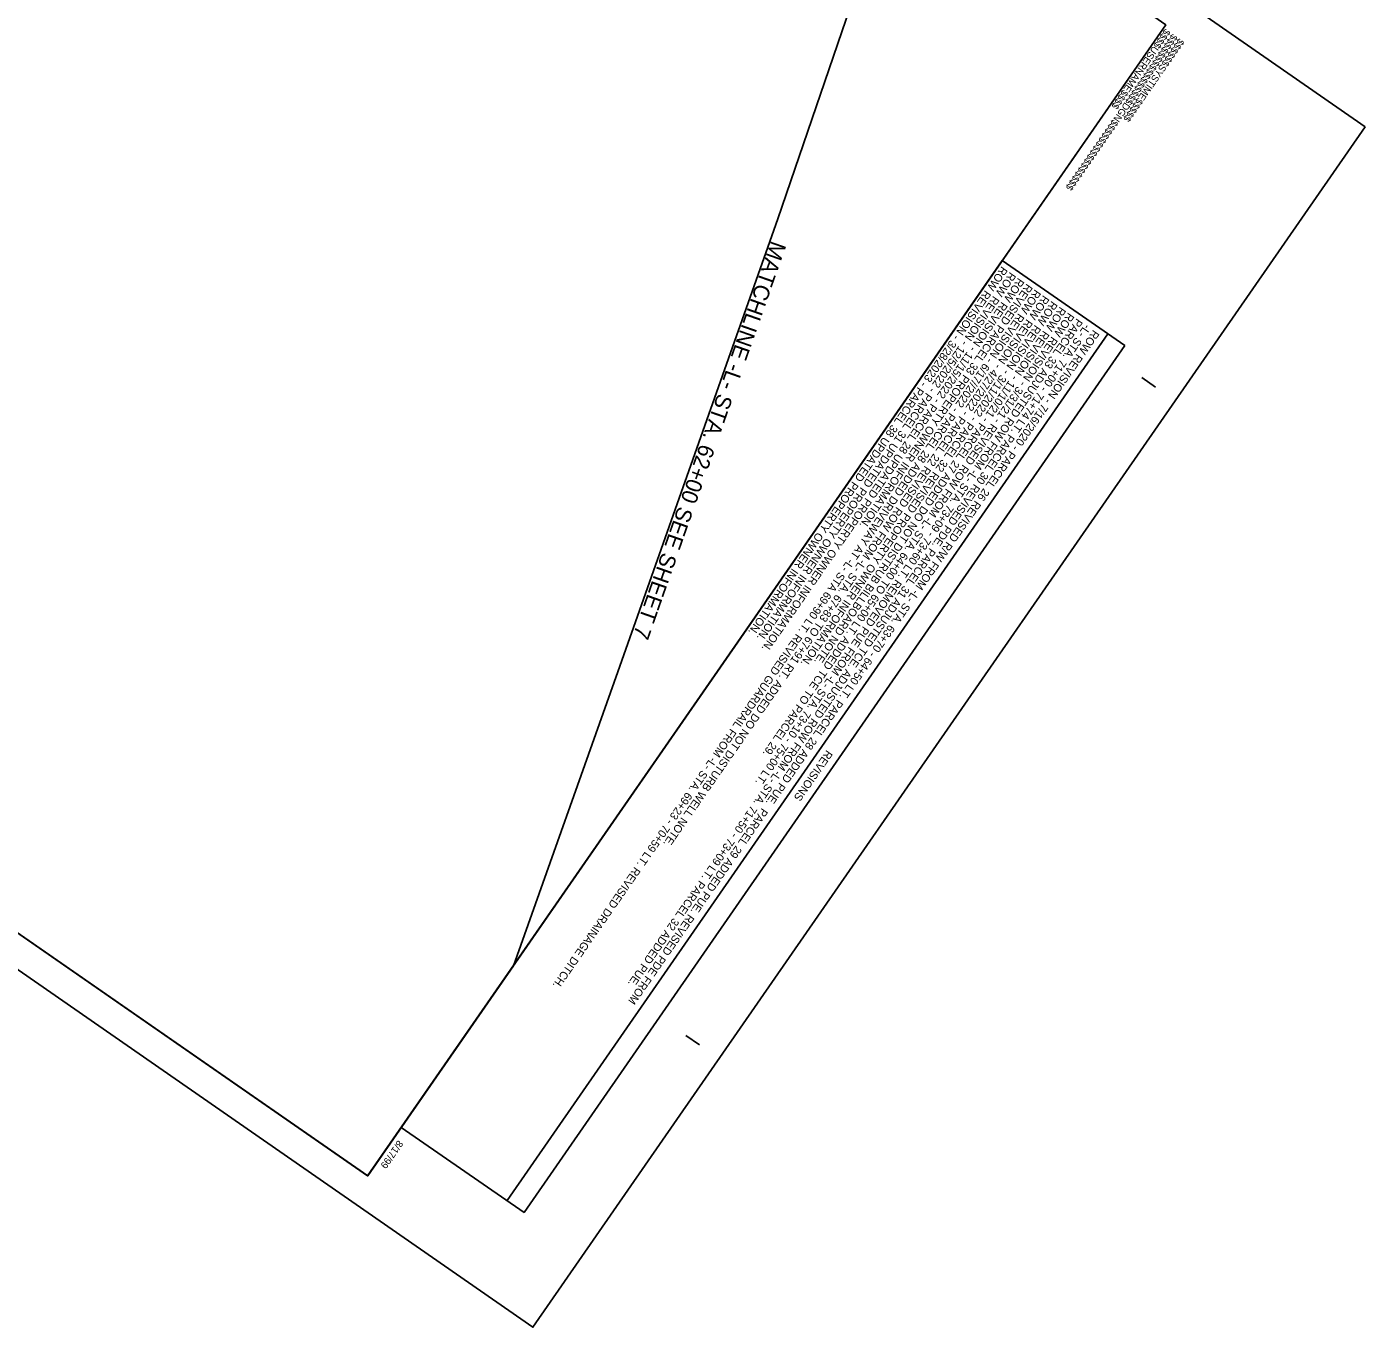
# Model space of a CAD drawing. Extents: x 478372 to 480379, y 492840 to 494699.
# Drawn here: x 479376 to 480379, y 492840 to 493814 of the extents above; entities that cross this region are included whole.
import ezdxf

# ---------------------------------------------------------------- set-up
doc = ezdxf.new("R2010")
doc.units = 0
for name, color, linetype in [('Matchline', 7, 'Continuous'), ('Matchline Text', 7, 'Continuous'), ('Sheet Block Revision CELL', 7, 'Continuous'), ('Sheet Clip Boundary CELL', 7, 'Continuous'), ('Sheet Plan CELL', 7, 'Continuous'), ('Sheet Plot Border Outside CELL', 7, 'Continuous')]:
    doc.layers.add(name, color=color, linetype=linetype)

msp = doc.modelspace()

# ---------------------------------------------------------------- linework, layer by layer
at = {"layer": 'Matchline'}
msp.add_line((479938.9, 493670.6), (479819.1, 493331.1), dxfattribs=at)
at = {"layer": 'Sheet Block Revision CELL'}
msp.add_line((480186.5, 493584.3), (479735.9, 492934.7), dxfattribs=at)
msp.add_lwpolyline([(480199.3, 493575.5), (479748.7, 492925.8), (479656.6, 492989.6), (480107.3, 493639.3)], close=True, dxfattribs=at)
at = {"layer": 'Sheet Clip Boundary CELL'}
msp.add_lwpolyline([(479740.7, 493110.7), (479819.1, 493331.1), (479938.9, 493670.6), (480035, 493951.1), (479137.5, 494573.7), (479091.9, 494507.9), (479078.6, 494420.5), (478969, 494336.5), (478682.9, 494117.9), (478570.3, 494055.3), (478497.8, 493950.7), (478662.1, 493836.7), (478563.2, 493694.1), (479631.4, 492953.2)], close=True, dxfattribs=at)
at = {"layer": 'Sheet Plan CELL'}
for p, q in [((480222.2, 493544.4), (480211.9, 493551.5)), ((479880.2, 493051.4), (479869.9, 493058.5)), ((479631.3, 492953.2), (479631.3, 492953.2))]:
    msp.add_line(p, q, dxfattribs=at)
for points in [[(478398.8, 493808.2), (479631.3, 492953.2), (480229.8, 493815.9), (478997.3, 494670.9)], [(480229.8, 493815.9), (479631.4, 492953.2), (478563.2, 493694.1), (478648.7, 493817.4), (478484.4, 493931.4), (478997.3, 494670.9)]]:
    msp.add_lwpolyline(points, close=True, dxfattribs=at)
at = {"layer": 'Sheet Plot Border Outside CELL'}
msp.add_lwpolyline([(480379.4, 493739.5), (478996.2, 494699.1), (478372.1, 493799.4), (479755.3, 492839.8)], close=True, dxfattribs=at)

# ---------------------------------------------------------------- texts
at = {"layer": 'Matchline Text'}
msp.add_text('MATCHLINE -L- STA. 62+00 SEE SHEET 7', height=12, rotation=250.6658, dxfattribs=at).set_placement((479934.2, 493654.7))
at = {"layer": 'Sheet Block Revision CELL'}
for s, p in [('ROW REVISION - 3/28/2023 - PARCEL 38 UPDATED PROPERTY OWNER INFORMATION.  ', (480106.8, 493635.4)), ('ROW REVISION - 12/5/2022 - PARCEL 31 UPDATED PROPERTY OWNER INFORMATION.', (480113.1, 493631.1)), ('ROW REVISION - 6/17//2022 - PARCEL 28 ADDED DRIVEWAY AT -L- STA 69+90 LT. REVISED GUARDRAIL FROM -L- STA. 69+23 - 70+59 LT. REVISED DRAINAGE DITCH.', (480131.8, 493618.1)), ('ROW REVISION - 11/15/2022 - PARCEL 28 UPDATED PROPERTY OWNER INFORMATION. ', (480119.3, 493626.7)), ('REVISED PARCEL 33 PROPERTY OWNER INFORMATION.', (480125.6, 493622.4)), ('ROW REVISION - 4/27/2022 - PARCEL 22 REVISED ROW FROM -L- STA. 67+83 TO 67+91 RT. ADDED DO NOT DISTURB WELL NOTE.', (480138.1, 493613.7)), ('ROW REVISION - 3/11/2022 - PARCEL 32 REVISED PROPERTY OWNER INFORMATION.  ', (480144.3, 493609.4)), ('ROW REVISION - 3/31/21 - REVISED ROW FROM -L- STA. 64+00 TO 65+00 LT. ADDED TCE TO PARCEL 29.', (480156.8, 493600.7)), ('ROW REVISION - 11/10/21 - PARCEL 27 ADDED DO NOT DISTRUB BILLBOARD NOTE.  ', (480150.6, 493605.1)), ('-L- STA. 71+00 - 71+74 LT. PARCEL 30 REVISED PDE. PARCEL 31 ADJUSTED TCE. ADJUSTED ROW FROM -L- STA. 71+50 - 73+09 LT. PARCEL 32 ADDED PUE.', (480169.3, 493592.1)), ('PARCEL 33 ADJUSTED ROW FROM -L- STA. 73+09 - 73+60 LT. REMOVED PUE FROM -L- STA. 73+10 - 75+00 LT. ', (480163.1, 493596.4)), ('ROW REVISION - 7/16/2020 - PARCEL 26 REVISED R/W FROM -L- STA. 63+70 - 64+50 LT. PARCEL 28 ADDED PUE.  PARCEL 29 ADDED PUE. REVISED PDE FROM', (480175.6, 493587.7)), ('REVISIONS', (479975.6, 493272.8))]:
    msp.add_text(s, height=6, rotation=235.2516, dxfattribs=at).set_placement(p)
at = {"layer": 'Sheet Plan CELL'}
for s, p in [('$$$$$$$$$$$$$$$$DGN$$$$$$$$$$$$$$$$', (480234.8, 493809.6)), ('$$$$USERNAME$$$$', (480229.4, 493813.4)), ('$$$$$$SYSTIME$$$$$', (480239.8, 493806.2)), ('8/17/99', (479654.1, 492980.3))]:
    msp.add_text(s, height=5.25, rotation=235.2516, dxfattribs=at).set_placement(p)

doc.saveas('drawing.dxf')
